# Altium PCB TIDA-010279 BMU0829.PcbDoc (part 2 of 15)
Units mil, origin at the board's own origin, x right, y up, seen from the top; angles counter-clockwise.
Board outline 11269.69 x 4438.98 mil, 4 copper layers (Top Layer, Signal Layer 1, Signal Layer 2, Bottom Layer), stack 61.6 mil thick; 1494 components, 725 nets, 3766 pads, 2728 vias.
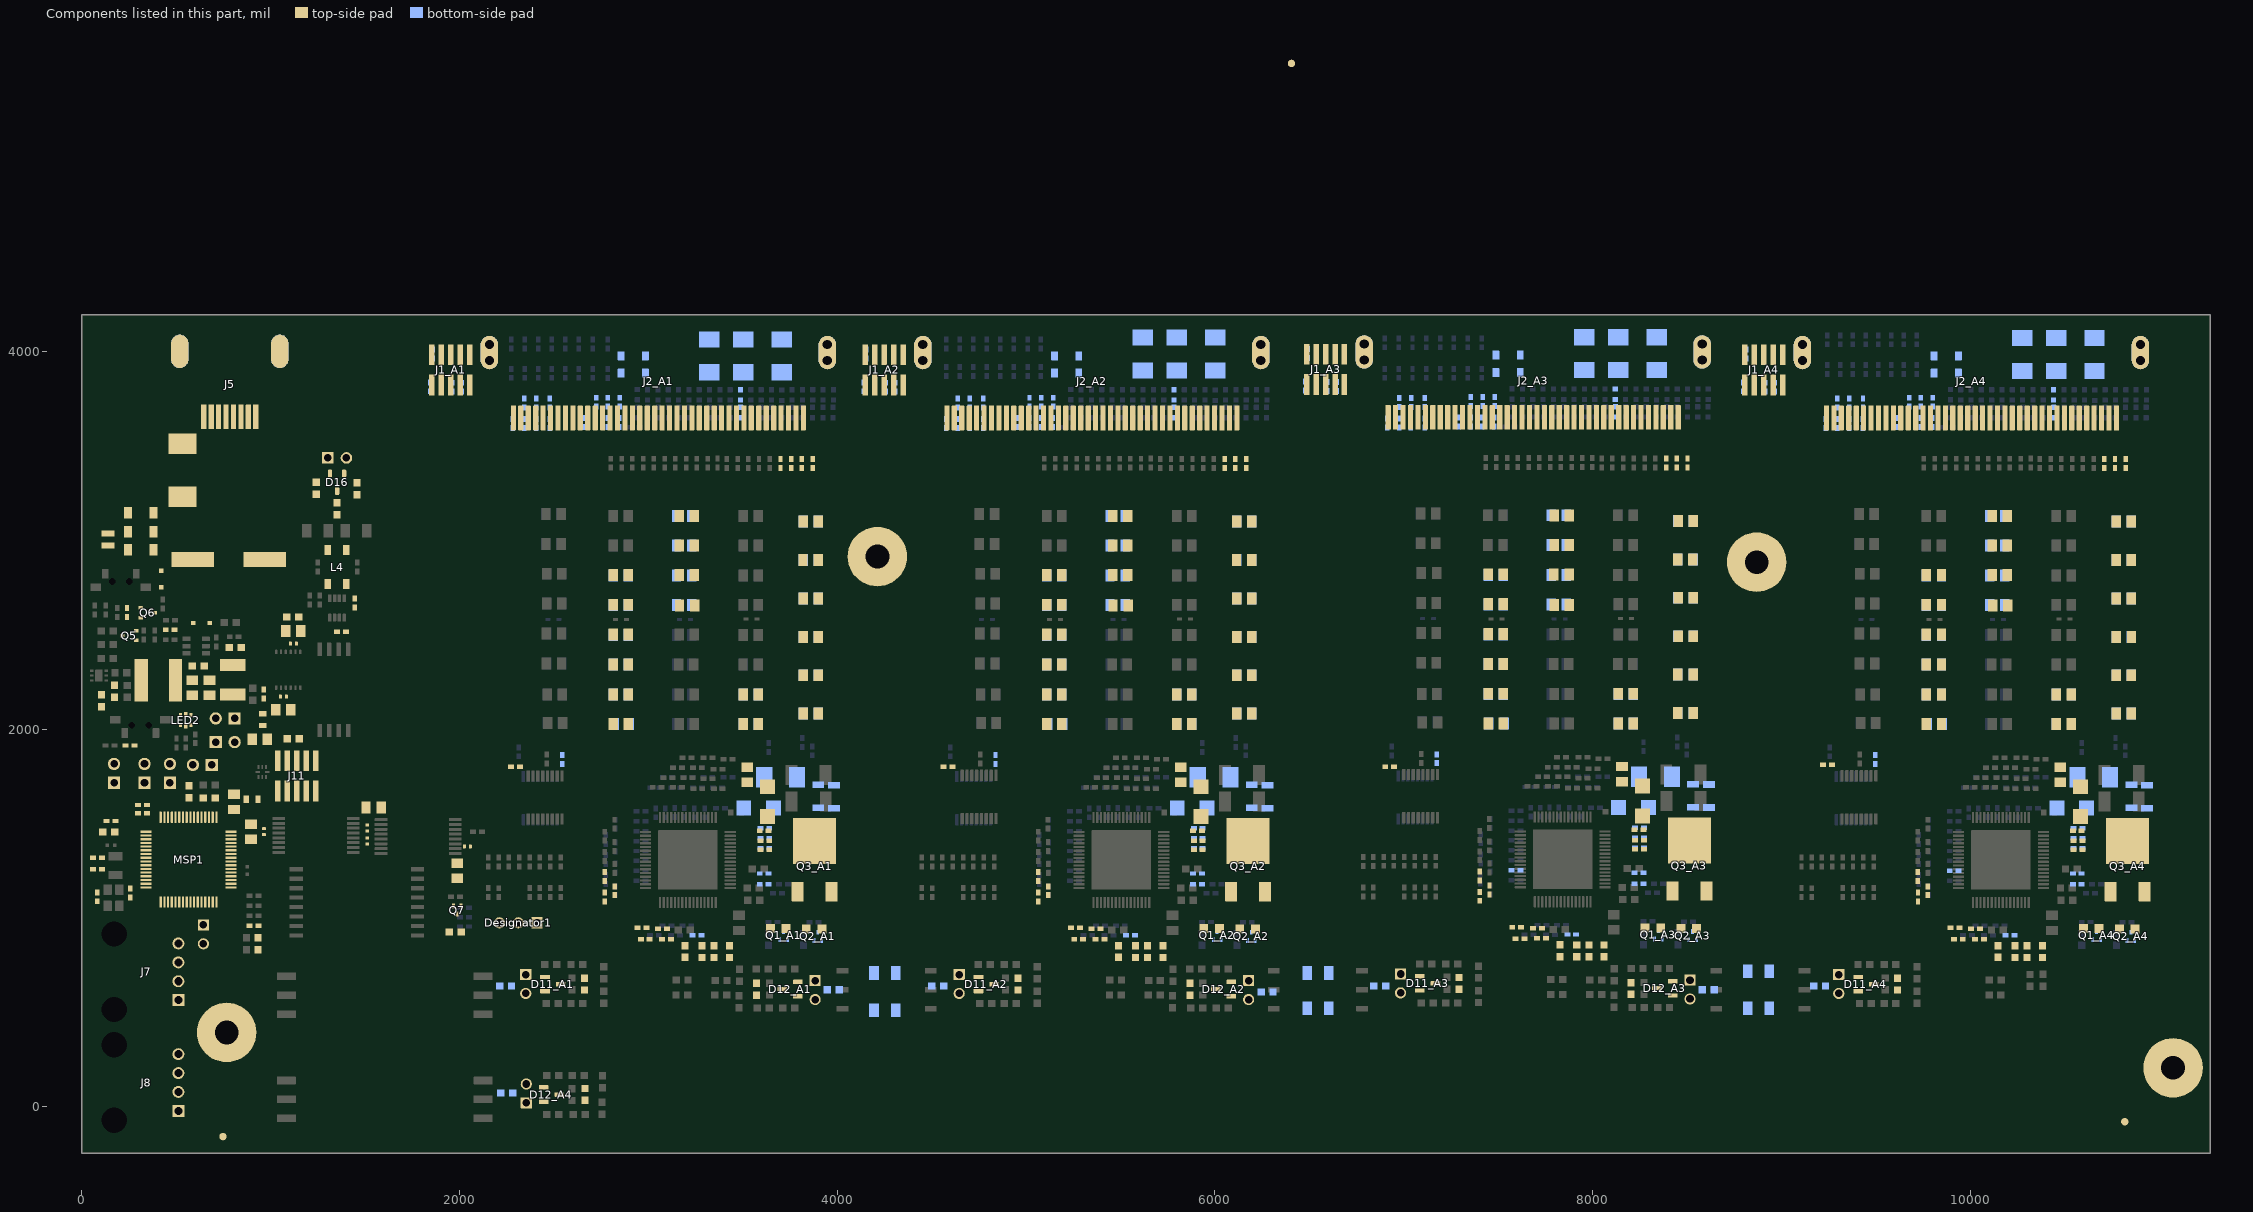
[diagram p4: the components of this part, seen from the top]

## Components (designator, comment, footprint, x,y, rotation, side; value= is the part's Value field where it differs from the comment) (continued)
C97_A3 "GCM155R71H104KE02D" 0402 7593.71,1252.59 r180 bottom value=0.1uF (schematic designator C97)
C97_A4 "GCM155R71H104KE02D" 0402 9913.94,1249.38 r180 bottom value=0.1uF (schematic designator C97)
C98_A1 "GCM155R71H472KA37D" 0402 2769.59,1219.43 r270 top value=4700pF (schematic designator C98)
C98_A2 "GCM155R71H472KA37D" 0402 5064.61,1219.43 r270 top value=4700pF (schematic designator C98)
C98_A3 "GCM155R71H472KA37D" 0402 7401.21,1222.64 r270 top value=4700pF (schematic designator C98)
C98_A4 "GCM155R71H472KA37D" 0402 9721.44,1219.43 r270 top value=4700pF (schematic designator C98)
C99_A1 "CGA3E2X7R2A223K080AA" FP-CGA3E2X7R2A223K080AA_0603-MFG 3488.75,3676.14 r90 bottom value=22nF (schematic designator C99)
C99_A2 "CGA3E2X7R2A223K080AA" FP-CGA3E2X7R2A223K080AA_0603-MFG 5783.76,3676.14 r90 bottom value=22nF (schematic designator C99)
C99_A3 "CGA3E2X7R2A223K080AA" FP-CGA3E2X7R2A223K080AA_0603-MFG 8120.36,3679.34 r90 bottom value=22nF (schematic designator C99)
C99_A4 "CGA3E2X7R2A223K080AA" FP-CGA3E2X7R2A223K080AA_0603-MFG 10440.59,3676.14 r90 bottom value=22nF (schematic designator C99)
C100_A1 "CGA3E2X7R2A223K080AA" FP-CGA3E2X7R2A223K080AA_0603-MFG 3488.04,3769.17 r90 bottom value=22nF (schematic designator C100)
C100_A2 "CGA3E2X7R2A223K080AA" FP-CGA3E2X7R2A223K080AA_0603-MFG 5783.06,3769.17 r90 bottom value=22nF (schematic designator C100)
C100_A3 "CGA3E2X7R2A223K080AA" FP-CGA3E2X7R2A223K080AA_0603-MFG 8119.66,3772.38 r90 bottom value=22nF (schematic designator C100)
C100_A4 "CGA3E2X7R2A223K080AA" FP-CGA3E2X7R2A223K080AA_0603-MFG 10439.89,3769.17 r90 bottom value=22nF (schematic designator C100)
C101_A1 "GCM155R71H472KA37D" 0402 2821.79,1144.09 r270 top value=4700pF (schematic designator C101)
C101_A2 "GCM155R71H472KA37D" 0402 5116.8,1144.09 r270 top value=4700pF (schematic designator C101)
C101_A3 "GCM155R71H472KA37D" 0402 7453.4,1147.3 r270 top value=4700pF (schematic designator C101)
C101_A4 "GCM155R71H472KA37D" 0402 9773.63,1144.09 r270 top value=4700pF (schematic designator C101)
C102_A1 "GCM155R71H472KA37D" 0402 2770.21,1111.63 r270 top value=4700pF (schematic designator C102)
C102_A2 "GCM155R71H472KA37D" 0402 5065.23,1111.63 r270 top value=4700pF (schematic designator C102)
C102_A3 "GCM155R71H472KA37D" 0402 7401.82,1114.83 r270 top value=4700pF (schematic designator C102)
C102_A4 "GCM155R71H472KA37D" 0402 9722.05,1111.63 r270 top value=4700pF (schematic designator C102)
C103_A1 "GCM155R71H104KE02D" 0402 3257.38,909.3 r0 bottom value=0.1uF (schematic designator C103)
C103_A2 "GCM155R71H104KE02D" 0402 5552.4,909.3 r0 bottom value=0.1uF (schematic designator C103)
C103_A3 "GCM155R71H104KE02D" 0402 7888.99,912.51 r0 bottom value=0.1uF (schematic designator C103)
C103_A4 "GCM155R71H104KE02D" 0402 10209.22,909.3 r0 bottom value=0.1uF (schematic designator C103)
C104_A1 "GCM155R71H472KA37D" 0402 2965.83,947.96 r0 top value=4700pF (schematic designator C104)
C104_A2 "GCM155R71H472KA37D" 0402 5260.84,947.96 r0 top value=4700pF (schematic designator C104)
C104_A3 "GCM155R71H472KA37D" 0402 7597.44,951.17 r0 top value=4700pF (schematic designator C104)
C104_A4 "GCM155R71H472KA37D" 0402 9917.67,947.96 r0 top value=4700pF (schematic designator C104)
C105_A1 "GCM155R71H472KA37D" 0402 2983.59,887.19 r0 top value=4700pF (schematic designator C105)
C105_A2 "GCM155R71H472KA37D" 0402 5278.61,887.19 r0 top value=4700pF (schematic designator C105)
C105_A3 "GCM155R71H472KA37D" 0402 7615.2,890.4 r0 top value=4700pF (schematic designator C105)
C105_A4 "GCM155R71H472KA37D" 0402 9935.43,887.19 r0 top value=4700pF (schematic designator C105)
C106_A1 "GCM155R71H472KA37D" 0402 3075.53,942.93 r0 top value=4700pF (schematic designator C106)
C106_A2 "GCM155R71H472KA37D" 0402 5370.55,942.93 r0 top value=4700pF (schematic designator C106)
C106_A3 "GCM155R71H472KA37D" 0402 7707.15,946.14 r0 top value=4700pF (schematic designator C106)
C106_A4 "GCM155R71H472KA37D" 0402 10027.38,942.93 r0 top value=4700pF (schematic designator C106)
C107_A1 "GCM155R71H472KA37D" 0402 3096.49,888.51 r0 top value=4700pF (schematic designator C107)
C107_A2 "GCM155R71H472KA37D" 0402 5391.5,888.51 r0 top value=4700pF (schematic designator C107)
C107_A3 "GCM155R71H472KA37D" 0402 7728.1,891.71 r0 top value=4700pF (schematic designator C107)
C107_A4 "GCM155R71H472KA37D" 0402 10048.33,888.51 r0 top value=4700pF (schematic designator C107)
C108_A1 "GCM155R71H104KE02D" 0402 2478.31,3617.56 r90 bottom value=0.1uF (schematic designator C108)
C108_A2 "GCM155R71H104KE02D" 0402 4773.32,3617.56 r90 bottom value=0.1uF (schematic designator C108)
C108_A3 "GCM155R71H104KE02D" 0402 7109.92,3620.76 r90 bottom value=0.1uF (schematic designator C108)
C108_A4 "GCM155R71H104KE02D" 0402 9430.15,3617.56 r90 bottom value=0.1uF (schematic designator C108)
C109_A1 "GCM155R71H104KE02D" 0402 2846.81,3622.34 r90 bottom value=0.1uF (schematic designator C109)
C109_A2 "GCM155R71H104KE02D" 0402 5141.83,3622.34 r90 bottom value=0.1uF (schematic designator C109)
C109_A3 "GCM155R71H104KE02D" 0402 7478.42,3625.55 r90 bottom value=0.1uF (schematic designator C109)
C109_A4 "GCM155R71H104KE02D" 0402 9798.65,3622.34 r90 bottom value=0.1uF (schematic designator C109)
C110_A1 "GCM155R71H104KE02D" 0402 3613.46,1178.02 r0 bottom value=0.1uF (schematic designator C110)
C110_A2 "GCM155R71H104KE02D" 0402 5908.48,1178.02 r0 bottom value=0.1uF (schematic designator C110)
C110_A3 "GCM155R71H104KE02D" 0402 8245.08,1181.23 r0 bottom value=0.1uF (schematic designator C110)
C110_A4 "GCM155R71H104KE02D" 0402 10565.31,1178.02 r0 bottom value=0.1uF (schematic designator C110)
C111_A1 "GCM155R71H104KE02D" 0402 2479.2,3725.82 r90 bottom value=0.1uF (schematic designator C111)
C111_A2 "GCM155R71H104KE02D" 0402 4774.22,3725.82 r90 bottom value=0.1uF (schematic designator C111)
C111_A3 "GCM155R71H104KE02D" 0402 7110.82,3729.03 r90 bottom value=0.1uF (schematic designator C111)
C111_A4 "GCM155R71H104KE02D" 0402 9431.05,3725.82 r90 bottom value=0.1uF (schematic designator C111)
C112_A1 "GCM155R71H104KE02D" 0402 2848.51,3730.61 r90 bottom value=0.1uF (schematic designator C112)
C112_A2 "GCM155R71H104KE02D" 0402 5143.53,3730.61 r90 bottom value=0.1uF (schematic designator C112)
C112_A3 "GCM155R71H104KE02D" 0402 7480.13,3733.82 r90 bottom value=0.1uF (schematic designator C112)
C112_A4 "GCM155R71H104KE02D" 0402 9800.36,3730.61 r90 bottom value=0.1uF (schematic designator C112)
C113_A1 "GCM155R71H104KE02D" 0402 1859.8,3985.59 r270 bottom value=0.1uF (schematic designator C113)
C113_A2 "GCM155R71H104KE02D" 0402 4154.81,3985.59 r270 bottom value=0.1uF (schematic designator C113)
C113_A3 "GCM155R71H104KE02D" 0402 6491.41,3988.8 r270 bottom value=0.1uF (schematic designator C113)
C113_A4 "GCM155R71H104KE02D" 0402 8811.64,3985.59 r270 bottom value=0.1uF (schematic designator C113)
C114_A1 "GCM155R71H104KE02D" 0402 3613.46,1235.37 r0 bottom value=0.1uF (schematic designator C114)
C114_A2 "GCM155R71H104KE02D" 0402 5908.48,1235.37 r0 bottom value=0.1uF (schematic designator C114)
C114_A3 "GCM155R71H104KE02D" 0402 8245.08,1238.57 r0 bottom value=0.1uF (schematic designator C114)
C114_A4 "GCM155R71H104KE02D" 0402 10565.31,1235.37 r0 bottom value=0.1uF (schematic designator C114)
C115_A1 "GCM155R71H104KE02D" 0402 3616.52,1409.33 r180 top value=0.1uF (schematic designator C115)
C115_A2 "GCM155R71H104KE02D" 0402 5911.54,1409.33 r180 top value=0.1uF (schematic designator C115)
C115_A3 "GCM155R71H104KE02D" 0402 8248.14,1412.54 r180 top value=0.1uF (schematic designator C115)
C115_A4 "GCM155R71H104KE02D" 0402 10568.37,1409.33 r180 top value=0.1uF (schematic designator C115)
C116_A1 "GCM155R71H104KE02D" 0402 2405.97,3617.56 r90 bottom value=0.1uF (schematic designator C116)
C116_A2 "GCM155R71H104KE02D" 0402 4700.98,3617.56 r90 bottom value=0.1uF (schematic designator C116)
C116_A3 "GCM155R71H104KE02D" 0402 7037.58,3620.76 r90 bottom value=0.1uF (schematic designator C116)
C116_A4 "GCM155R71H104KE02D" 0402 9357.81,3617.56 r90 bottom value=0.1uF (schematic designator C116)
C117_A1 "GCM155R71H104KE02D" 0402 2784.32,3622.34 r90 bottom value=0.1uF (schematic designator C117)
C117_A2 "GCM155R71H104KE02D" 0402 5079.33,3622.34 r90 bottom value=0.1uF (schematic designator C117)
C117_A3 "GCM155R71H104KE02D" 0402 7415.93,3625.55 r90 bottom value=0.1uF (schematic designator C117)
C117_A4 "GCM155R71H104KE02D" 0402 9736.16,3622.34 r90 bottom value=0.1uF (schematic designator C117)
C118_A1 "GCM155R71H104KE02D" 0402 1845.97,3812.37 r90 bottom value=0.1uF (schematic designator C118)
C118_A2 "GCM155R71H104KE02D" 0402 4140.99,3812.37 r90 bottom value=0.1uF (schematic designator C118)
C118_A3 "GCM155R71H104KE02D" 0402 6477.58,3815.58 r90 bottom value=0.1uF (schematic designator C118)
C118_A4 "GCM155R71H104KE02D" 0402 8797.81,3812.37 r90 bottom value=0.1uF (schematic designator C118)
C119_A1 "GCM155R71H104KE02D" 0402 3616.52,1474.8 r0 bottom value=0.1uF (schematic designator C119)
C119_A2 "GCM155R71H104KE02D" 0402 5911.54,1474.8 r0 bottom value=0.1uF (schematic designator C119)
C119_A3 "GCM155R71H104KE02D" 0402 8248.14,1478.01 r0 bottom value=0.1uF (schematic designator C119)
C119_A4 "GCM155R71H104KE02D" 0402 10568.37,1474.8 r0 bottom value=0.1uF (schematic designator C119)
C120_A1 "GCM155R71H104KE02D" 0402 2297.24,1801.18 r180 top value=0.1uF (schematic designator C120)
C120_A2 "GCM155R71H104KE02D" 0402 4586.61,1801.18 r180 top value=0.1uF (schematic designator C120)
C120_A3 "GCM155R71H104KE02D" 0402 6925.2,1801.18 r180 top value=0.1uF (schematic designator C120)
C120_A4 "GCM155R71H104KE02D" 0402 9242.13,1811.02 r180 top value=0.1uF (schematic designator C120)
C121_A1 "GCM155R71H104KE02D" 0402 2406.66,3725.82 r90 bottom value=0.1uF (schematic designator C121)
C121_A2 "GCM155R71H104KE02D" 0402 4701.68,3725.82 r90 bottom value=0.1uF (schematic designator C121)
C121_A3 "GCM155R71H104KE02D" 0402 7038.28,3729.03 r90 bottom value=0.1uF (schematic designator C121)
C121_A4 "GCM155R71H104KE02D" 0402 9358.51,3725.82 r90 bottom value=0.1uF (schematic designator C121)
C122_A1 "GCM155R71H104KE02D" 0402 2785.82,3730.61 r90 bottom value=0.1uF (schematic designator C122)
C122_A2 "GCM155R71H104KE02D" 0402 5080.83,3730.61 r90 bottom value=0.1uF (schematic designator C122)
C122_A3 "GCM155R71H104KE02D" 0402 7417.43,3733.82 r90 bottom value=0.1uF (schematic designator C122)
C122_A4 "GCM155R71H104KE02D" 0402 9737.66,3730.61 r90 bottom value=0.1uF (schematic designator C122)
C123_A1 "GCM155R71H104KE02D" 0402 2005.4,3982.92 r270 bottom value=0.1uF (schematic designator C123)
C123_A2 "GCM155R71H104KE02D" 0402 4300.42,3982.92 r270 bottom value=0.1uF (schematic designator C123)
C123_A3 "GCM155R71H104KE02D" 0402 6637.01,3986.12 r270 bottom value=0.1uF (schematic designator C123)
C123_A4 "GCM155R71H104KE02D" 0402 8957.24,3982.92 r270 bottom value=0.1uF (schematic designator C123)
C124_A1 "GCM155R71H104KE02D" 0402 3616.52,1422.9 r0 bottom value=0.1uF (schematic designator C124)
C124_A2 "GCM155R71H104KE02D" 0402 5911.54,1422.9 r0 bottom value=0.1uF (schematic designator C124)
C124_A3 "GCM155R71H104KE02D" 0402 8248.14,1426.11 r0 bottom value=0.1uF (schematic designator C124)
C124_A4 "GCM155R71H104KE02D" 0402 10568.37,1422.9 r0 bottom value=0.1uF (schematic designator C124)
C125_A1 "885012208118" WCAP-CSGP_1206_L3.2W1.6H1.25 3899.74,1644.24 r270 bottom (schematic designator C125)
C125_A2 "885012208118" WCAP-CSGP_1206_L3.2W1.6H1.25 6194.75,1644.24 r270 bottom (schematic designator C125)
C125_A3 "885012208118" WCAP-CSGP_1206_L3.2W1.6H1.25 8531.35,1647.45 r270 bottom (schematic designator C125)
C125_A4 "885012208118" WCAP-CSGP_1206_L3.2W1.6H1.25 10851.58,1644.24 r270 bottom (schematic designator C125)
C126_A1 "GCM155R71H104KE02D" 0402 2343.47,3617.56 r90 bottom value=0.1uF (schematic designator C126)
C126_A2 "GCM155R71H104KE02D" 0402 4638.49,3617.56 r90 bottom value=0.1uF (schematic designator C126)
C126_A3 "GCM155R71H104KE02D" 0402 6975.09,3620.76 r90 bottom value=0.1uF (schematic designator C126)
C126_A4 "GCM155R71H104KE02D" 0402 9295.32,3617.56 r90 bottom value=0.1uF (schematic designator C126)
C127_A1 "GCM155R71H104KE02D" 0402 2721.82,3622.34 r90 bottom value=0.1uF (schematic designator C127)
C127_A2 "GCM155R71H104KE02D" 0402 5016.84,3622.34 r90 bottom value=0.1uF (schematic designator C127)
C127_A3 "GCM155R71H104KE02D" 0402 7353.43,3625.55 r90 bottom value=0.1uF (schematic designator C127)
C127_A4 "GCM155R71H104KE02D" 0402 9673.66,3622.34 r90 bottom value=0.1uF (schematic designator C127)
C128_A1 "GCM155R71H104KE02D" 0402 2011.97,3810.12 r90 bottom value=0.1uF (schematic designator C128)
C128_A2 "GCM155R71H104KE02D" 0402 4306.99,3810.12 r90 bottom value=0.1uF (schematic designator C128)
C128_A3 "GCM155R71H104KE02D" 0402 6643.58,3813.32 r90 bottom value=0.1uF (schematic designator C128)
C128_A4 "GCM155R71H104KE02D" 0402 8963.81,3810.12 r90 bottom value=0.1uF (schematic designator C128)
C129_A1 "GCM155R71H104KE02D" 0402 3616.52,1369.24 r0 bottom value=0.1uF (schematic designator C129)
C129_A2 "GCM155R71H104KE02D" 0402 5911.54,1369.24 r0 bottom value=0.1uF (schematic designator C129)
C129_A3 "GCM155R71H104KE02D" 0402 8248.14,1372.45 r0 bottom value=0.1uF (schematic designator C129)
C129_A4 "GCM155R71H104KE02D" 0402 10568.37,1369.24 r0 bottom value=0.1uF (schematic designator C129)
C130_A1 "GCM155R71H104KE02D" 0402 2343.97,3725.82 r90 bottom value=0.1uF (schematic designator C130)
C130_A2 "GCM155R71H104KE02D" 0402 4638.98,3725.82 r90 bottom value=0.1uF (schematic designator C130)
C130_A3 "GCM155R71H104KE02D" 0402 6975.58,3729.03 r90 bottom value=0.1uF (schematic designator C130)
C130_A4 "GCM155R71H104KE02D" 0402 9295.81,3725.82 r90 bottom value=0.1uF (schematic designator C130)
C131_A1 "GCM155R71H104KE02D" 0402 2723.12,3730.61 r90 bottom value=0.1uF (schematic designator C131)
C131_A2 "GCM155R71H104KE02D" 0402 5018.14,3730.61 r90 bottom value=0.1uF (schematic designator C131)
C131_A3 "GCM155R71H104KE02D" 0402 7354.73,3733.82 r90 bottom value=0.1uF (schematic designator C131)
C131_A4 "GCM155R71H104KE02D" 0402 9674.96,3730.61 r90 bottom value=0.1uF (schematic designator C131)
C132_A1 "GCM155R71H104KE02D" 0402 1961.97,3810.12 r90 bottom value=0.1uF (schematic designator C132)
C132_A2 "GCM155R71H104KE02D" 0402 4256.99,3810.12 r90 bottom value=0.1uF (schematic designator C132)
C132_A3 "GCM155R71H104KE02D" 0402 6593.58,3813.32 r90 bottom value=0.1uF (schematic designator C132)
C132_A4 "GCM155R71H104KE02D" 0402 8913.81,3810.12 r90 bottom value=0.1uF (schematic designator C132)
C133_A1 "GCM155R71H104KE02D" 0402 3613.46,1462.99 r0 top value=0.1uF (schematic designator C133)
C133_A2 "GCM155R71H104KE02D" 0402 5908.48,1462.99 r0 top value=0.1uF (schematic designator C133)
C133_A3 "GCM155R71H104KE02D" 0402 8245.08,1466.2 r0 top value=0.1uF (schematic designator C133)
C133_A4 "GCM155R71H104KE02D" 0402 10565.31,1462.99 r0 top value=0.1uF (schematic designator C133)
C135_A1 "GCM155R71H104KE02D" 0402 3616.52,1360.65 r180 top value=0.1uF (schematic designator C135)
C135_A2 "GCM155R71H104KE02D" 0402 5911.54,1360.65 r180 top value=0.1uF (schematic designator C135)
C135_A3 "GCM155R71H104KE02D" 0402 8248.14,1363.85 r180 top value=0.1uF (schematic designator C135)
C135_A4 "GCM155R71H104KE02D" 0402 10568.37,1360.65 r180 top value=0.1uF (schematic designator C135)
C136_A1 "GCM155R71H104KE02D" 0402 2280.98,3617.56 r90 bottom value=0.1uF (schematic designator C136)
C136_A2 "GCM155R71H104KE02D" 0402 4575.99,3617.56 r90 bottom value=0.1uF (schematic designator C136)
C136_A3 "GCM155R71H104KE02D" 0402 6912.59,3620.76 r90 bottom value=0.1uF (schematic designator C136)
C136_A4 "GCM155R71H104KE02D" 0402 9232.82,3617.56 r90 bottom value=0.1uF (schematic designator C136)
C137_A1 "GCM155R71H104KE02D" 0402 2659.32,3622.34 r90 bottom value=0.1uF (schematic designator C137)
C137_A2 "GCM155R71H104KE02D" 0402 4954.34,3622.34 r90 bottom value=0.1uF (schematic designator C137)
C137_A3 "GCM155R71H104KE02D" 0402 7290.94,3625.55 r90 bottom value=0.1uF (schematic designator C137)
C137_A4 "GCM155R71H104KE02D" 0402 9611.17,3622.34 r90 bottom value=0.1uF (schematic designator C137)
C138_A1 "GCM155R71H104KE02D" 0402 1904.13,3812.1 r90 bottom value=0.1uF (schematic designator C138)
C138_A2 "GCM155R71H104KE02D" 0402 4199.15,3812.1 r90 bottom value=0.1uF (schematic designator C138)
C138_A3 "GCM155R71H104KE02D" 0402 6535.75,3815.31 r90 bottom value=0.1uF (schematic designator C138)
C138_A4 "GCM155R71H104KE02D" 0402 8855.98,3812.1 r90 bottom value=0.1uF (schematic designator C138)
C140_A1 "GCM155R71H104KE02D" 0402 2543.08,1839.7 r90 bottom value=0.1uF (schematic designator C140)
C140_A2 "GCM155R71H104KE02D" 0402 4838.1,1839.7 r90 bottom value=0.1uF (schematic designator C140)
C140_A3 "GCM155R71H104KE02D" 0402 7174.69,1842.91 r90 bottom value=0.1uF (schematic designator C140)
C140_A4 "GCM155R71H104KE02D" 0402 9494.92,1839.7 r90 bottom value=0.1uF (schematic designator C140)
C147_A1 "GCM188R71H103KA37D" 0603 2661.35,650.13 r90 top value=0.01uF (schematic designator C147)
C147_A2 "GCM188R71H103KA37D" 0603 4956.37,650.13 r90 top value=0.01uF (schematic designator C147)
C147_A3 "GCM188R71H103KA37D" 0603 7292.96,653.33 r90 top value=0.01uF (schematic designator C147)
C147_A4 "GCM188R71H103KA37D" 0603 9613.19,650.13 r90 top value=0.01uF (schematic designator C147)
C148_A1 "GCM188R71H103KA37D" 0603 3571.8,623.34 r270 top value=0.01uF (schematic designator C148)
C148_A2 "GCM188R71H103KA37D" 0603 5866.81,623.34 r270 top value=0.01uF (schematic designator C148)
C148_A3 "GCM188R71H103KA37D" 0603 8203.41,626.54 r270 top value=0.01uF (schematic designator C148)
C148_A4 "GCM188R71H103KA37D" 0603 2665.33,65.64 r90 top value=0.01uF (schematic designator C148)
C149_A1 "CL10B221JB8NNNC" 0603 3283.85,822.24 r270 top value=220pF (schematic designator C149)
C149_A2 "CL10B221JB8NNNC" 0603 5578.86,822.24 r270 top value=220pF (schematic designator C149)
C149_A3 "CL10B221JB8NNNC" 0603 7915.46,825.45 r270 top value=220pF (schematic designator C149)
C149_A4 "CL10B221JB8NNNC" 0603 10235.69,822.24 r270 top value=220pF (schematic designator C149)
C150_A1 "CL10B221JB8NNNC" 0603 3347.63,822.3 r270 top value=220pF (schematic designator C150)
C150_A2 "CL10B221JB8NNNC" 0603 5642.65,822.3 r270 top value=220pF (schematic designator C150)
C150_A3 "CL10B221JB8NNNC" 0603 7979.24,825.51 r270 top value=220pF (schematic designator C150)
C150_A4 "CL10B221JB8NNNC" 0603 10299.47,822.3 r270 top value=220pF (schematic designator C150)
C151_A1 "CL10B221JB8NNNC" 0603 3429.04,822.3 r270 top value=220pF (schematic designator C151)
C151_A2 "CL10B221JB8NNNC" 0603 5724.05,822.3 r270 top value=220pF (schematic designator C151)
C151_A3 "CL10B221JB8NNNC" 0603 8060.65,825.51 r270 top value=220pF (schematic designator C151)
C151_A4 "CL10B221JB8NNNC" 0603 10380.88,822.3 r270 top value=220pF (schematic designator C151)
C152_A1 "CL10B221JB8NNNC" 0603 3194.84,822.43 r270 top value=220pF (schematic designator C152)
C152_A2 "CL10B221JB8NNNC" 0603 5489.86,822.43 r270 top value=220pF (schematic designator C152)
C152_A3 "CL10B221JB8NNNC" 0603 7826.46,825.64 r270 top value=220pF (schematic designator C152)
C152_A4 "CL10B221JB8NNNC" 0603 10146.69,822.43 r270 top value=220pF (schematic designator C152)
C153 "12061A222JAT2A" 1206 4251.97,708.66 r180 bottom value=2200pF
C154 "12061A222JAT2A" 1206 6545.28,708.66 r180 bottom value=2200pF
C155 "12061A222JAT2A" 1206 8877.95,718.5 r180 bottom value=2200pF
C156 "GCM1885C1H101JA16J" 0603 2244.09,639.76 r180 bottom value=100pF
C157 "GCM1885C1H101JA16J" 0603 3979.86,620.08 r0 bottom value=100pF
C158 "GCM1885C1H101JA16J" 0603 4532.72,640.91 r180 bottom value=100pF
C159 "GCM1885C1H101JA16J" 0603 6275.62,608.32 r0 bottom value=100pF
C160 "GCM1885C1H101JA16J" 0603 6872.05,639.76 r180 bottom value=100pF
C161 "GCM1885C1H101JA16J" 0603 8612.2,620.08 r0 bottom value=100pF
C162 "GCM1885C1H101JA16J" 0603 9200.79,639.76 r180 bottom value=100pF
C163 "12061A222JAT2A" 1206 4251.97,511.81 r0 bottom value=2200pF
C164 "12061A222JAT2A" 1206 6545.28,521.65 r0 bottom value=2200pF
C165 "12061A222JAT2A" 1206 8877.95,521.65 r0 bottom value=2200pF
C166 "GCM1885C1H101JA16J" 0603 2249.93,72.99 r180 bottom value=100pF
C167 "GRM188R60J106ME84" 0603 143.61,1454.71 r180 top value=10uF
C168 "GRM155R61H104ME14D" 0402 154.29,1513.33 r180 top value=0.1uF
C169 "GRM155R60J474KE19D" 0402 322.32,1598.07 r180 top value=0.47uF
C170 "GRM155R61H104ME14D" 0402 322.32,1555.39 r180 top value=0.1uF
C171 "GRM155R61C103KA01D" 0402 255.11,1913.14 r0 top value=0.01uF
C172 "C1608X5R1E105K080AC" 0603 674.85,1634.48 r0 top value=1uF
C173 "C1608X5R1E105K080AC" 0603 568.65,1667.95 r90 top value=1uF
C174 "GRM1555C1H220JA01D" 0402 83.14,1318.58 r0 top value=22pF
C175 "GRM1555C1H220JA01D" 0402 255.91,1131.89 r270 top value=22pF
C176 "GRM1555C1H220JA01D" 0402 82.99,1112.19 r90 top value=22pF
C177 "GRM1555C1H220JA01D" 0402 83.14,1258.51 r0 top value=22pF
C178 "EEV-TG2A470Q" Panasonic_H13 778.42,2897.5 r0 top value=47uF
C179 "C3216X7S2A225K160AB" 1206_180 312.36,3145.66 r0 top value=2.2uF
C180 "C3216X7S2A225K160AB" 1206_180 312.36,3044.8 r0 top value=2.2uF
C181 "C3216X7S2A225K160AB" 1206_180 312.36,2949.24 r0 top value=2.2uF
C182 "CGA3E2C0G1H220J080AA" 0603 812.25,2431.89 r180 top value=22pF
C183 "GRM21BZ71E106KE15L" 0805_HV 585.31,2219.73 r90 top value=10uF
C184 "CGA8P1X7R1E226M250KC" 1812_280 799.53,2261.54 r90 top value=22uF
C185 "GRM21BZ71A226ME15L" 0805_HV 942.76,1946.08 r0 top value=22uF
C186 "GRM21BZ71A226ME15L" 0805_HV 807.09,1614.17 r270 top value=22uF
C187 "GCM155R71H153KA55D" FP-GCM155R71H153KA55D_0402-MFG 1512.52,1475.78 r90 top value=15nF
C189 "GRM21BZ71A226ME15L" 0805_HV 1545.28,1584.65 r180 top value=22uF
C190 "GCM155R71H153KA55D" FP-GCM155R71H153KA55D_0402-MFG 1512.52,1406.88 r270 top value=15nF
C191_A1 "885012208118" WCAP-CSGP_1206_L3.2W1.6H1.25 3983.15,1642.23 r270 bottom (schematic designator C191)
C191_A2 "885012208118" WCAP-CSGP_1206_L3.2W1.6H1.25 6278.17,1642.23 r270 bottom (schematic designator C191)
C191_A3 "885012208118" WCAP-CSGP_1206_L3.2W1.6H1.25 8614.77,1645.44 r270 bottom (schematic designator C191)
C191_A4 "885012208118" WCAP-CSGP_1206_L3.2W1.6H1.25 10935,1642.23 r270 bottom (schematic designator C191)
C196 "GCM155R71H104KE02D" 0402 239.74,2618.05 r270 top value=0.1uF
C197 "GCM188R71C105KA64D" 0603 173.32,2200.57 r270 top value=1uF
C198 "GRT188R61C475KE13D" 0603 104.46,2149.67 r270 top value=4.7uF
C199 "GCM155R71H104KE02D" 0402 468.51,2527.01 r0 top value=0.1uF
C201 "06035C104KAT2A" 0603 1120.28,1948.73 r0 top value=0.1uF
C202 "06035C104KAT2A" 0603 1117.96,2593.41 r180 top value=0.1uF
C203 "GCM155R71H153KA55D" FP-GCM155R71H153KA55D_0402-MFG 1120.83,2452.76 r0 top value=15nF
C204 "GRM21BZ71A226ME15L" 0805_HV 1119.53,2518.39 r180 top value=22uF
C205 "GRM21BZ71A226ME15L" 0805_HV 1067.02,2102.33 r0 top value=22uF
C206 "GCM155R71H153KA55D" FP-GCM155R71H153KA55D_0402-MFG 1067.64,2172.12 r180 top value=15nF
C207 "GCM155R71H222KA37D" 0402 964.57,2185.04 r270 top value=2200pF
C211 "GCM155R71H153KA55D" FP-GCM155R71H153KA55D_0402-MFG 2041.56,1378.74 r180 top value=15nF
C212 "GRM21BZ71A226ME15L" 0805_HV 1988.19,1250.63 r270 top value=22uF
C213 "GRM21BZ71A226ME15L" 0805_HV 895.67,1456.69 r270 top value=22uF
C214 "GCM155R71H153KA55D" FP-GCM155R71H153KA55D_0402-MFG 964.57,1456.69 r90 top value=15nF
C215 "GCM155R71H222KA37D" 0402 911.42,958.55 r0 top value=2200pF
C216 "06035C104KAT2A" 0603 933.76,863.04 r90 top value=0.1uF
C217 "06035C104KAT2A" 0603 1978.35,925.2 r0 top value=0.1uF
C218 "GCM1885C1H680JA16D" 0603 1241.81,3274.57 r270 top value=68pF
C219 "GCM188R72A472KA37D" 0603 1351.97,3167.42 r90 top value=4700pF
C220 "GCM155R71A104KA55D" 0402 1375.07,2515.62 r0 top value=0.1uF
C221 "GCM1885C1H680JA16D" 0603 1457.91,3273.15 r90 top value=68pF
C222 "GCM155R71A104KA55D" 0402 1446.1,2667.99 r270 top value=0.1uF
CBoot1 "06035C104KAT2A" 0603 617.6,2334.37 r180 top value=0.1uF
CO1 "08055C104JAT2A" 0805_HV 676.04,2219.27 r90 top value=0.1uF
D1_A1 "ES1C-13-F" SMA 3584,1582.22 r0 bottom value=150V (schematic designator D1)
D1_A2 "ES1C-13-F" SMA 5879.02,1582.22 r0 bottom value=150V (schematic designator D1)
D1_A3 "ES1C-13-F" SMA 8215.62,1585.42 r0 bottom value=150V (schematic designator D1)
D1_A4 "ES1C-13-F" SMA 10535.85,1582.22 r0 bottom value=150V (schematic designator D1)
D2_A1 "LTST-C170KGKT" LTST-C170KGKT_Green 3687.03,943.19 r0 top value=Green (schematic designator D2)
D2_A2 "LTST-C170KGKT" LTST-C170KGKT_Green 5982.04,943.19 r0 top value=Green (schematic designator D2)
D2_A3 "LTST-C170KGKT" LTST-C170KGKT_Green 8318.64,946.39 r0 top value=Green (schematic designator D2)
D2_A4 "LTST-C170KGKT" LTST-C170KGKT_Green 10638.87,943.19 r0 top value=Green (schematic designator D2)
D3_A1 "LTST-C170KGKT" LTST-C170KGKT_Green 3877.43,941.68 r0 top value=Green (schematic designator D3)
D3_A2 "LTST-C170KGKT" LTST-C170KGKT_Green 6172.45,941.67 r0 top value=Green (schematic designator D3)
D3_A3 "LTST-C170KGKT" LTST-C170KGKT_Green 8509.04,944.88 r0 top value=Green (schematic designator D3)
D3_A4 "LTST-C170KGKT" LTST-C170KGKT_Green 10829.27,941.67 r0 top value=Green (schematic designator D3)
D4_A1 "SMD16PL-TP" FP-SMD16PL-TP_SOD123FL-MFG 2919.97,3976.38 r0 bottom (schematic designator D4)
D4_A2 "SMD16PL-TP" FP-SMD16PL-TP_SOD123FL-MFG 5214.99,3976.38 r0 bottom (schematic designator D4)
D4_A3 "SMD16PL-TP" FP-SMD16PL-TP_SOD123FL-MFG 7551.59,3979.59 r0 bottom (schematic designator D4)
D4_A4 "SMD16PL-TP" FP-SMD16PL-TP_SOD123FL-MFG 9871.82,3976.38 r0 bottom (schematic designator D4)
D5_A1 "SMD16PL-TP" FP-SMD16PL-TP_SOD123FL-MFG 2919.97,3884.6 r180 bottom (schematic designator D5)
D5_A2 "SMD16PL-TP" FP-SMD16PL-TP_SOD123FL-MFG 5214.99,3884.6 r180 bottom (schematic designator D5)
D5_A3 "SMD16PL-TP" FP-SMD16PL-TP_SOD123FL-MFG 7551.59,3887.81 r180 bottom (schematic designator D5)
D5_A4 "SMD16PL-TP" FP-SMD16PL-TP_SOD123FL-MFG 9871.82,3884.6 r180 bottom (schematic designator D5)
D6_A1 "SMBJ85A-13-F" SMB 3706.58,3976.38 r270 bottom value=85V (schematic designator D6)
D6_A2 "SMBJ85A-13-F" SMB 6001.28,3985.41 r270 bottom value=85V (schematic designator D6)
D6_A3 "SMBJ85A-13-F" SMB 8338.19,3987.59 r270 bottom value=85V (schematic designator D6)
D6_A4 "SMBJ85A-13-F" SMB 10656.64,3983.96 r270 bottom value=85V (schematic designator D6)
D7_A1 "SMBJ85A-13-F" SMB 3323.11,3976.38 r270 bottom value=85V (schematic designator D7)
D7_A2 "SMBJ85A-13-F" SMB 5617.8,3985.41 r270 bottom value=85V (schematic designator D7)
D7_A3 "SMBJ85A-13-F" SMB 7954.72,3987.59 r270 bottom value=85V (schematic designator D7)
D7_A4 "SMBJ85A-13-F" SMB 10273.17,3983.96 r270 bottom value=85V (schematic designator D7)
D8_A1 "SMBJ85A-13-F" SMB 3503.08,3976.38 r270 bottom value=85V (schematic designator D8)
D8_A2 "SMBJ85A-13-F" SMB 5797.78,3985.41 r270 bottom value=85V (schematic designator D8)
D8_A3 "SMBJ85A-13-F" SMB 8134.69,3987.59 r270 bottom value=85V (schematic designator D8)
D8_A4 "SMBJ85A-13-F" SMB 10453.14,3983.96 r270 bottom value=85V (schematic designator D8)
D9_A1 "SMAJ85A" SMA 3631.54,1616.25 r270 top value=85V (schematic designator D9)
D9_A2 "SMAJ85A" SMA 5926.55,1616.25 r270 top value=85V (schematic designator D9)
D9_A3 "SMAJ85A" SMA 8263.14,1619.46 r270 top value=85V (schematic designator D9)
D9_A4 "SMAJ85A" SMA 10583.37,1616.25 r270 top value=85V (schematic designator D9)
D10_A1 "SMBJ85A-13-F" SMB 3700.7,1744.01 r0 bottom value=85V (schematic designator D10)
D10_A2 "SMBJ85A-13-F" SMB 5995.71,1744.01 r0 bottom value=85V (schematic designator D10)
D10_A3 "SMBJ85A-13-F" SMB 8332.31,1747.22 r0 bottom value=85V (schematic designator D10)
D10_A4 "SMBJ85A-13-F" SMB 10652.54,1744.01 r0 bottom value=85V (schematic designator D10)
D11_A1 "ESD652DBZR" DBZ0003A-MFG 2494.5,650.13 r0 top (schematic designator D11)
D11_A2 "ESD652DBZR" DBZ0003A-MFG 4789.51,650.13 r0 top (schematic designator D11)
D11_A3 "ESD652DBZR" DBZ0003A-MFG 7126.11,653.33 r0 top (schematic designator D11)
D11_A4 "ESD652DBZR" DBZ0003A-MFG 9446.34,650.13 r0 top (schematic designator D11)
D12_A1 "ESD652DBZR" DBZ0003A-MFG 3750.16,623.73 r180 top (schematic designator D12)
D12_A2 "ESD652DBZR" DBZ0003A-MFG 6045.17,623.73 r180 top (schematic designator D12)
D12_A3 "ESD652DBZR" DBZ0003A-MFG 8381.77,626.94 r180 top (schematic designator D12)
D12_A4 "ESD652DBZR" DBZ0003A-MFG 2486.98,65.24 r0 top (schematic designator D12)
D13 "SMCJ33CA" SMC_Bi 533.47,3370.59 r90 top value=33V
D14 "1N4148WS-7-F" SOD-323 634.11,2561.74 r0 top value=75V
D15 "1N4148WS-7-F" SOD-323 421.01,2794.53 r90 top value=75V
D16 "NUP2105LT1G" SOT-23 1351.97,3306.61 r270 top value=24V
Designator1 "Comment" CONN_PEC03SAAN 2311.42,974.41 r180 top
FID1 "Fiducial" Fiducial10-20 6405.12,5524.33 r0 top
FID2 "Fiducial" Fiducial10-20 748.03,-157.48 r0 top
FID3 "Fiducial" Fiducial10-20 10816.93,-78.74 r0 top
H1 "NY PMS 440 0025 PH" "NY PMS 440 0025 PH" 4212.6,2913.39 r0 top locked
H2 "NY PMS 440 0025 PH" "NY PMS 440 0025 PH" 8868.11,2883.86 r0 top locked
H3 "NY PMS 440 0025 PH" "NY PMS 440 0025 PH" 767.72,393.7 r0 top locked
H4 "NY PMS 440 0025 PH" "NY PMS 440 0025 PH" 11072.83,206.69 r0 top locked
H5 "1902C" Keystone_1902C 4212.6,2913.39 r180 bottom locked
H6 "1902C" Keystone_1902C 8868.11,2883.86 r180 bottom locked
H7 "1902C" Keystone_1902C 767.72,393.7 r180 bottom locked
H8 "1902C" Keystone_1902C 11072.83,206.69 r180 bottom locked
H9 "SJ-5303 (CLEAR)" Bumpon_SJ5003Transparent 6555.12,5354.33 r180 bottom
H10 "SJ-5303 (CLEAR)" Bumpon_SJ5003Transparent 7696.85,5295.28 r180 bottom
H11 "SJ-5303 (CLEAR)" Bumpon_SJ5003Transparent 7148.27,5333.31 r180 bottom
H12 "SJ-5303 (CLEAR)" Bumpon_SJ5003Transparent 8208.66,5295.28 r180 bottom
J1_A1 "FTSH-105-01-L-DV-K" Samtec_FTSH-105-01-x-DV-K 1953.97,3901.37 r90 top (schematic designator J1)
J1_A2 "FTSH-105-01-L-DV-K" Samtec_FTSH-105-01-x-DV-K 4248.99,3901.37 r90 top (schematic designator J1)
J1_A3 "FTSH-105-01-L-DV-K" Samtec_FTSH-105-01-x-DV-K 6585.58,3904.57 r90 top (schematic designator J1)
J1_A4 "FTSH-105-01-L-DV-K" Samtec_FTSH-105-01-x-DV-K 8905.81,3901.37 r90 top (schematic designator J1)
J2_A1 "141114-214010" FP-141114-214010_HDR40-MFG 3053.26,3950.27 r180 top (schematic designator J2)
J2_A2 "141114-214010" FP-141114-214010_HDR40-MFG 5348.27,3950.27 r180 top (schematic designator J2)
J2_A3 "141114-214010" FP-141114-214010_HDR40-MFG 7684.87,3953.48 r180 top (schematic designator J2)
J2_A4 "141114-214010" FP-141114-214010_HDR40-MFG 10005.1,3950.27 r180 top (schematic designator J2)
J3_A1 "PEC02SAAN" CONN_PEC02SAAN 2350.88,650.27 r270 top (schematic designator J3)
J3_A2 "PEC02SAAN" CONN_PEC02SAAN 4645.87,650.27 r270 top (schematic designator J3)
J3_A3 "PEC02SAAN" CONN_PEC02SAAN 6982.47,653.48 r270 top (schematic designator J3)
J3_A4 "PEC02SAAN" CONN_PEC02SAAN 9302.7,650.27 r270 top (schematic designator J3)
J4_A1 "PEC02SAAN" CONN_PEC02SAAN 3883.27,618.03 r270 top (schematic designator J4)
J4_A2 "PEC02SAAN" CONN_PEC02SAAN 6178.29,618.03 r270 top (schematic designator J4)
J4_A3 "PEC02SAAN" CONN_PEC02SAAN 8514.89,621.24 r270 top (schematic designator J4)
J4_A4 "PEC02SAAN" CONN_PEC02SAAN 2353.86,70.95 r90 top (schematic designator J4)
J5 "141114-210810" FP-141114-210810_CONN_HDR16-MFG 783.84,3956.69 r180 top
J7 "70551-0038" Molex_70551-0038 511.81,714.92 r180 top
J8 "70551-0038" Molex_70551-0038 511.81,128.74 r180 top
J9 "90120-0122" CONN_90120-0122 171.17,1765.6 r90 top
J11 "FTSH-105-01-L-DV-K" Samtec_FTSH-105-01-x-DV-K 1138.86,1751.69 r270 top
J12 "90120-0122" CONN_90120-0122 759.8,1931.31 r0 top
J13 "90120-0122" CONN_90120-0122 759.36,2056.51 r180 top
J16 "PEC02SAAN" CONN_PEC02SAAN 644.34,913.32 r270 top
J17 "90120-0122" CONN_90120-0122 638.73,1810.3 r180 top
J18 "90120-0122" CONN_90120-0122 467.18,1765.6 r90 top
J20 "90120-0122" CONN_90120-0122 332.35,1765.6 r90 top
J21 "HTSW-102-09-G-S" Samtec_HTSW-102-09-x-S 1351.61,3435.53 r0 top
L2 "74479276210C" WE-PMCI_0806_L2W1.6H1 139,3003.31 r270 top
L3 "74404064330" WE-LQS_6045 406.31,2257.6 r180 top
L4 "ACT45B-510-2P-TL003" ACT45B_NoSilk 1351.96,2857.79 r90 top value=51uH
L5 "74479763222" WE-PMI_0603_L1.6W0.8H0.8 958.44,2050.07 r90 top
L6 "74479763222" WE-PMI_0603_L1.6W0.8H0.8 902.16,1629.66 r0 top
LBL1 "THT-14-423-10" Label_650x200 4891.73,39.37 r180 top
LED2 "19-337/R6GHBHC-A01/2T" 19-337_RGB 551.18,2047.24 r270 top value=RGB
Logo1 "Texas Instruments" TI_Stacked_Overlay_Small 6102.36,68.9 r0 top
Logo2 "CE Mark" CE_Mark_5mm 11463.49,523.08 r0 top
Logo3 "FCC disclaimer" FCC_disclaimer 1889.76,2312.99 r90 top
Logo4 "WEEE logo" WEEE_Minimum 7726.38,88.58 r0 top
MSP1 "MSPM0G3507SPM" PM0064A-MFG 565.6,1308.97 r180 top
Q1_A1 "RE1C002UNTCL" SC-89 3716.01,907.76 r90 bottom value=20V (schematic designator Q1)
Q1_A2 "RE1C002UNTCL" SC-89 6011.03,907.76 r90 bottom value=20V (schematic designator Q1)
Q1_A3 "RE1C002UNTCL" SC-89 8347.62,910.97 r90 bottom value=20V (schematic designator Q1)
Q1_A4 "RE1C002UNTCL" SC-89 10667.85,907.76 r90 bottom value=20V (schematic designator Q1)
Q2_A1 "RE1C002UNTCL" SC-89 3897.24,903.07 r90 bottom value=20V (schematic designator Q2)
Q2_A2 "RE1C002UNTCL" SC-89 6192.26,903.07 r90 bottom value=20V (schematic designator Q2)
Q2_A3 "RE1C002UNTCL" SC-89 8528.86,906.28 r90 bottom value=20V (schematic designator Q2)
Q2_A4 "RE1C002UNTCL" SC-89 10849.09,903.07 r90 bottom value=20V (schematic designator Q2)
Q3_A1 "CMP-0000504-4" DPAK 3880.05,1273.19 r90 top value="150 V" (schematic designator Q3)
Q3_A2 "CMP-0000504-4" DPAK 6175.07,1273.19 r90 top value="150 V" (schematic designator Q3)
Q3_A3 "CMP-0000504-4" DPAK 8511.66,1276.39 r90 top value="150 V" (schematic designator Q3)
Q3_A4 "CMP-0000504-4" DPAK 10831.89,1273.19 r90 top value="150 V" (schematic designator Q3)
Q5 "BSS84AKW,115" SOT-323 250.98,2495.33 r180 top value=-50V
Q6 "BC847BW,115" SOT-323 349.67,2615.55 r0 top value="45 V"
Q7 "RE1C002UNTCL" SC-89 1988.58,1041.54 r270 top value=20V
R1_A1 "HPCR0805J68R0KT" 0805_HV 2854.78,2816.48 r0 top value=68 (schematic designator R1)
R1_A2 "HPCR0805J68R0KT" 0805_HV 5149.8,2816.48 r0 top value=68 (schematic designator R1)
R1_A3 "HPCR0805J68R0KT" 0805_HV 7486.4,2819.69 r0 top value=68 (schematic designator R1)
R1_A4 "HPCR0805J68R0KT" 0805_HV 9806.63,2816.48 r0 top value=68 (schematic designator R1)
R2_A1 "HPCR0805J68R0KT" 0805_HV 3542.76,2184.04 r0 top value=68 (schematic designator R2)
R2_A2 "HPCR0805J68R0KT" 0805_HV 5837.78,2184.04 r0 top value=68 (schematic designator R2)
R2_A3 "HPCR0805J68R0KT" 0805_HV 8174.38,2187.25 r0 top value=68 (schematic designator R2)
R2_A4 "HPCR0805J68R0KT" 0805_HV 10494.6,2184.04 r0 top value=68 (schematic designator R2)
R3_A1 "HPCR0805J68R0KT" 0805_HV 3859.45,2895.38 r0 bottom value=68 (schematic designator R3)
R3_A2 "HPCR0805J68R0KT" 0805_HV 6154.47,2895.38 r0 bottom value=68 (schematic designator R3)
R3_A3 "HPCR0805J68R0KT" 0805_HV 8491.06,2898.58 r0 bottom value=68 (schematic designator R3)
R3_A4 "HPCR0805J68R0KT" 0805_HV 10811.29,2895.38 r0 bottom value=68 (schematic designator R3)
R4_A1 "HPCR0805J68R0KT" 0805_HV 2854.78,2658.37 r0 top value=68 (schematic designator R4)
R4_A2 "HPCR0805J68R0KT" 0805_HV 5149.8,2658.37 r0 top value=68 (schematic designator R4)
R4_A3 "HPCR0805J68R0KT" 0805_HV 7486.4,2661.58 r0 top value=68 (schematic designator R4)
R4_A4 "HPCR0805J68R0KT" 0805_HV 9806.63,2658.37 r0 top value=68 (schematic designator R4)
R5_A1 "HPCR0805J68R0KT" 0805_HV 3543.08,2025.93 r0 bottom value=68 (schematic designator R5)
R5_A2 "HPCR0805J68R0KT" 0805_HV 5838.1,2025.93 r0 bottom value=68 (schematic designator R5)
R5_A3 "HPCR0805J68R0KT" 0805_HV 8174.69,2029.14 r0 bottom value=68 (schematic designator R5)
R5_A4 "HPCR0805J68R0KT" 0805_HV 10494.92,2025.93 r0 bottom value=68 (schematic designator R5)
R6_A1 "HPCR0805J68R0KT" 0805_HV 3858.98,2895.5 r0 top value=68 (schematic designator R6)
R6_A2 "HPCR0805J68R0KT" 0805_HV 6154,2895.5 r0 top value=68 (schematic designator R6)
R6_A3 "HPCR0805J68R0KT" 0805_HV 8490.59,2898.71 r0 top value=68 (schematic designator R6)
R6_A4 "HPCR0805J68R0KT" 0805_HV 10810.82,2895.5 r0 top value=68 (schematic designator R6)
R7_A1 "HPCR0805J68R0KT" 0805_HV 2854.76,2656.12 r0 bottom value=68 (schematic designator R7)
R7_A2 "HPCR0805J68R0KT" 0805_HV 5149.78,2656.12 r0 bottom value=68 (schematic designator R7)
R7_A3 "HPCR0805J68R0KT" 0805_HV 7486.37,2659.32 r0 bottom value=68 (schematic designator R7)
R7_A4 "HPCR0805J68R0KT" 0805_HV 9806.6,2656.12 r0 bottom value=68 (schematic designator R7)
R8_A1 "HPCR0805J68R0KT" 0805_HV 3543.08,2183.48 r0 bottom value=68 (schematic designator R8)
R8_A2 "HPCR0805J68R0KT" 0805_HV 5838.1,2183.48 r0 bottom value=68 (schematic designator R8)
R8_A3 "HPCR0805J68R0KT" 0805_HV 8174.69,2186.69 r0 bottom value=68 (schematic designator R8)
R8_A4 "HPCR0805J68R0KT" 0805_HV 10494.92,2183.48 r0 bottom value=68 (schematic designator R8)
R9_A1 "HPCR0805J68R0KT" 0805_HV 3860.14,3098.81 r0 top value=68 (schematic designator R9)
R9_A2 "HPCR0805J68R0KT" 0805_HV 6155.16,3098.81 r0 top value=68 (schematic designator R9)
R9_A3 "HPCR0805J68R0KT" 0805_HV 8491.76,3102.01 r0 top value=68 (schematic designator R9)
R9_A4 "HPCR0805J68R0KT" 0805_HV 10811.99,3098.81 r0 top value=68 (schematic designator R9)
R10_A1 "HPCR0805J68R0KT" 0805_HV 2854.76,2813.66 r0 bottom value=68 (schematic designator R10)
R10_A2 "HPCR0805J68R0KT" 0805_HV 5149.78,2813.66 r0 bottom value=68 (schematic designator R10)
R10_A3 "HPCR0805J68R0KT" 0805_HV 7486.37,2816.87 r0 bottom value=68 (schematic designator R10)
R10_A4 "HPCR0805J68R0KT" 0805_HV 9806.6,2813.66 r0 bottom value=68 (schematic designator R10)
R11_A1 "HPCR0805J68R0KT" 0805_HV 3542.76,2025.93 r0 top value=68 (schematic designator R11)
R11_A2 "HPCR0805J68R0KT" 0805_HV 5837.78,2025.93 r0 top value=68 (schematic designator R11)
R11_A3 "HPCR0805J68R0KT" 0805_HV 8174.38,2029.14 r0 top value=68 (schematic designator R11)
R11_A4 "HPCR0805J68R0KT" 0805_HV 10494.6,2025.93 r0 top value=68 (schematic designator R11)
R12_A1 "HPCR0805J68R0KT" 0805_HV 3859.45,3098.81 r0 bottom value=68 (schematic designator R12)
R12_A2 "HPCR0805J68R0KT" 0805_HV 6154.47,3098.81 r0 bottom value=68 (schematic designator R12)
R12_A3 "HPCR0805J68R0KT" 0805_HV 8491.06,3102.01 r0 bottom value=68 (schematic designator R12)
R12_A4 "HPCR0805J68R0KT" 0805_HV 10811.29,3098.81 r0 bottom value=68 (schematic designator R12)
R13_A1 "HPCR0805J68R0KT" 0805_HV 2854.78,2342.15 r0 top value=68 (schematic designator R13)
R13_A2 "HPCR0805J68R0KT" 0805_HV 5149.8,2342.15 r0 top value=68 (schematic designator R13)
R13_A3 "HPCR0805J68R0KT" 0805_HV 7486.4,2345.36 r0 top value=68 (schematic designator R13)
R13_A4 "HPCR0805J68R0KT" 0805_HV 9806.63,2342.15 r0 top value=68 (schematic designator R13)
R14_A1 "HPCR0805J68R0KT" 0805_HV 3203.94,3128.18 r0 top value=68 (schematic designator R14)
R14_A2 "HPCR0805J68R0KT" 0805_HV 5498.96,3128.18 r0 top value=68 (schematic designator R14)
R14_A3 "HPCR0805J68R0KT" 0805_HV 7835.55,3131.39 r0 top value=68 (schematic designator R14)
R14_A4 "HPCR0805J68R0KT" 0805_HV 10155.78,3128.18 r0 top value=68 (schematic designator R14)
R15_A1 "HPCR0805J68R0KT" 0805_HV 3859.45,2691.94 r0 bottom value=68 (schematic designator R15)
R15_A2 "HPCR0805J68R0KT" 0805_HV 6154.47,2691.94 r0 bottom value=68 (schematic designator R15)
R15_A3 "HPCR0805J68R0KT" 0805_HV 8491.06,2695.15 r0 bottom value=68 (schematic designator R15)
R15_A4 "HPCR0805J68R0KT" 0805_HV 10811.29,2691.94 r0 bottom value=68 (schematic designator R15)
R16_A1 "HPCR0805J68R0KT" 0805_HV 2854.78,2500.26 r0 top value=68 (schematic designator R16)
R16_A2 "HPCR0805J68R0KT" 0805_HV 5149.8,2500.26 r0 top value=68 (schematic designator R16)
R16_A3 "HPCR0805J68R0KT" 0805_HV 7486.4,2503.47 r0 top value=68 (schematic designator R16)
R16_A4 "HPCR0805J68R0KT" 0805_HV 9806.63,2500.26 r0 top value=68 (schematic designator R16)
R17_A1 "HPCR0805J68R0KT" 0805_HV 3189.11,2971.21 r0 bottom value=68 (schematic designator R17)
R17_A2 "HPCR0805J68R0KT" 0805_HV 5484.12,2971.21 r0 bottom value=68 (schematic designator R17)
R17_A3 "HPCR0805J68R0KT" 0805_HV 7820.72,2974.42 r0 bottom value=68 (schematic designator R17)
R17_A4 "HPCR0805J68R0KT" 0805_HV 10140.95,2971.21 r0 bottom value=68 (schematic designator R17)
R18_A1 "HPCR0805J68R0KT" 0805_HV 3859.45,2488.51 r0 bottom value=68 (schematic designator R18)
R18_A2 "HPCR0805J68R0KT" 0805_HV 6154.47,2488.51 r0 bottom value=68 (schematic designator R18)
R18_A3 "HPCR0805J68R0KT" 0805_HV 8491.06,2491.72 r0 bottom value=68 (schematic designator R18)
R18_A4 "HPCR0805J68R0KT" 0805_HV 10811.29,2488.51 r0 bottom value=68 (schematic designator R18)
R19_A1 "CRCW04021K00FKED" 0402 3870.27,3405.51 r270 top value=1.00k (schematic designator R19)
R19_A2 "CRCW04021K00FKED" 0402 6165.29,3405.51 r270 top value=1.00k (schematic designator R19)
R19_A3 "CRCW04021K00FKED" 0402 8501.88,3408.72 r270 top value=1.00k (schematic designator R19)
R19_A4 "CRCW04021K00FKED" 0402 10822.11,3405.51 r270 top value=1.00k (schematic designator R19)
R20_A1 "HPCR0805J68R0KT" 0805_HV 2854.76,2341.02 r0 bottom value=68 (schematic designator R20)
R20_A2 "HPCR0805J68R0KT" 0805_HV 5149.78,2341.02 r0 bottom value=68 (schematic designator R20)
R20_A3 "HPCR0805J68R0KT" 0805_HV 7486.37,2344.23 r0 bottom value=68 (schematic designator R20)
R20_A4 "HPCR0805J68R0KT" 0805_HV 9806.6,2341.02 r0 bottom value=68 (schematic designator R20)
R21_A1 "HPCR0805J68R0KT" 0805_HV 3203.94,2971.21 r0 top value=68 (schematic designator R21)
R21_A2 "HPCR0805J68R0KT" 0805_HV 5498.96,2971.21 r0 top value=68 (schematic designator R21)
R21_A3 "HPCR0805J68R0KT" 0805_HV 7835.55,2974.42 r0 top value=68 (schematic designator R21)
R21_A4 "HPCR0805J68R0KT" 0805_HV 10155.78,2971.21 r0 top value=68 (schematic designator R21)
R22_A1 "HPCR0805J68R0KT" 0805_HV 3860.17,2691.94 r0 top value=68 (schematic designator R22)
R22_A2 "HPCR0805J68R0KT" 0805_HV 6155.19,2691.94 r0 top value=68 (schematic designator R22)
R22_A3 "HPCR0805J68R0KT" 0805_HV 8491.78,2695.15 r0 top value=68 (schematic designator R22)
R22_A4 "HPCR0805J68R0KT" 0805_HV 10812.01,2691.94 r0 top value=68 (schematic designator R22)
R23_A1 "HPCR0805J68R0KT" 0805_HV 2854.76,2498.57 r0 bottom value=68 (schematic designator R23)
R23_A2 "HPCR0805J68R0KT" 0805_HV 5149.78,2498.57 r0 bottom value=68 (schematic designator R23)
R23_A3 "HPCR0805J68R0KT" 0805_HV 7486.37,2501.78 r0 bottom value=68 (schematic designator R23)
R23_A4 "HPCR0805J68R0KT" 0805_HV 9806.6,2498.57 r0 bottom value=68 (schematic designator R23)
R24_A1 "HPCR0805J68R0KT" 0805_HV 3189.11,3128.75 r0 bottom value=68 (schematic designator R24)
R24_A2 "HPCR0805J68R0KT" 0805_HV 5484.12,3128.75 r0 bottom value=68 (schematic designator R24)
R24_A3 "HPCR0805J68R0KT" 0805_HV 7820.72,3131.96 r0 bottom value=68 (schematic designator R24)
R24_A4 "HPCR0805J68R0KT" 0805_HV 10140.95,3128.75 r0 bottom value=68 (schematic designator R24)
R25_A1 "HPCR0805J68R0KT" 0805_HV 3860.57,2488.51 r0 top value=68 (schematic designator R25)
R25_A2 "HPCR0805J68R0KT" 0805_HV 6155.59,2488.51 r0 top value=68 (schematic designator R25)
R25_A3 "HPCR0805J68R0KT" 0805_HV 8492.18,2491.72 r0 top value=68 (schematic designator R25)
R25_A4 "HPCR0805J68R0KT" 0805_HV 10812.41,2488.51 r0 top value=68 (schematic designator R25)
R26_A1 "CRCW04021K00FKED" 0402 3813.4,3405.51 r270 top value=1.00k (schematic designator R26)
R26_A2 "CRCW04021K00FKED" 0402 6108.42,3405.51 r270 top value=1.00k (schematic designator R26)
R26_A3 "CRCW04021K00FKED" 0402 8445.02,3408.72 r270 top value=1.00k (schematic designator R26)
R26_A4 "CRCW04021K00FKED" 0402 10765.25,3405.51 r270 top value=1.00k (schematic designator R26)
R27_A1 "HPCR0805J68R0KT" 0805_HV 2854.78,2025.93 r0 top value=68 (schematic designator R27)
R27_A2 "HPCR0805J68R0KT" 0805_HV 5149.8,2025.93 r0 top value=68 (schematic designator R27)
R27_A3 "HPCR0805J68R0KT" 0805_HV 7486.4,2029.14 r0 top value=68 (schematic designator R27)
R27_A4 "HPCR0805J68R0KT" 0805_HV 9806.63,2025.93 r0 top value=68 (schematic designator R27)
R28_A1 "HPCR0805J68R0KT" 0805_HV 3203.13,2815.51 r0 top value=68 (schematic designator R28)
R28_A2 "HPCR0805J68R0KT" 0805_HV 5498.15,2815.51 r0 top value=68 (schematic designator R28)
R28_A3 "HPCR0805J68R0KT" 0805_HV 7834.75,2818.72 r0 top value=68 (schematic designator R28)
R28_A4 "HPCR0805J68R0KT" 0805_HV 10154.98,2815.51 r0 top value=68 (schematic designator R28)
R29_A1 "HPCR0805J68R0KT" 0805_HV 3859.45,2285.08 r0 top value=68 (schematic designator R29)
R29_A2 "HPCR0805J68R0KT" 0805_HV 6154.47,2285.08 r0 top value=68 (schematic designator R29)
R29_A3 "HPCR0805J68R0KT" 0805_HV 8491.06,2288.29 r0 top value=68 (schematic designator R29)
R29_A4 "HPCR0805J68R0KT" 0805_HV 10811.29,2285.08 r0 top value=68 (schematic designator R29)
R30_A1 "HPCR0805J68R0KT" 0805_HV 2854.78,2184.04 r0 top value=68 (schematic designator R30)
R30_A2 "HPCR0805J68R0KT" 0805_HV 5149.8,2184.04 r0 top value=68 (schematic designator R30)
R30_A3 "HPCR0805J68R0KT" 0805_HV 7486.4,2187.25 r0 top value=68 (schematic designator R30)
R30_A4 "HPCR0805J68R0KT" 0805_HV 9806.63,2184.04 r0 top value=68 (schematic designator R30)
R31_A1 "HPCR0805J68R0KT" 0805_HV 3189.11,2813.66 r0 bottom value=68 (schematic designator R31)
R31_A2 "HPCR0805J68R0KT" 0805_HV 5484.12,2813.66 r0 bottom value=68 (schematic designator R31)
R31_A3 "HPCR0805J68R0KT" 0805_HV 7820.72,2816.87 r0 bottom value=68 (schematic designator R31)
R31_A4 "HPCR0805J68R0KT" 0805_HV 10140.95,2813.66 r0 bottom value=68 (schematic designator R31)
R32_A1 "HPCR0805J68R0KT" 0805_HV 3859.45,2285.08 r0 bottom value=68 (schematic designator R32)
R32_A2 "HPCR0805J68R0KT" 0805_HV 6154.47,2285.08 r0 bottom value=68 (schematic designator R32)
R32_A3 "HPCR0805J68R0KT" 0805_HV 8491.06,2288.29 r0 bottom value=68 (schematic designator R32)
R32_A4 "HPCR0805J68R0KT" 0805_HV 10811.29,2285.08 r0 bottom value=68 (schematic designator R32)
R33_A1 "HPCR0805J68R0KT" 0805_HV 2854.76,2183.48 r0 bottom value=68 (schematic designator R33)
R33_A2 "HPCR0805J68R0KT" 0805_HV 5149.78,2183.48 r0 bottom value=68 (schematic designator R33)
R33_A3 "HPCR0805J68R0KT" 0805_HV 7486.37,2186.69 r0 bottom value=68 (schematic designator R33)
R33_A4 "HPCR0805J68R0KT" 0805_HV 9806.6,2183.48 r0 bottom value=68 (schematic designator R33)
R34_A1 "HPCR0805J68R0KT" 0805_HV 3205.08,2653.85 r0 top value=68 (schematic designator R34)
R34_A2 "HPCR0805J68R0KT" 0805_HV 5500.09,2653.85 r0 top value=68 (schematic designator R34)
R34_A3 "HPCR0805J68R0KT" 0805_HV 7836.69,2657.06 r0 top value=68 (schematic designator R34)
R34_A4 "HPCR0805J68R0KT" 0805_HV 10156.92,2653.85 r0 top value=68 (schematic designator R34)
R35_A1 "HPCR0805J68R0KT" 0805_HV 3859.45,2081.65 r0 bottom value=68 (schematic designator R35)
R35_A2 "HPCR0805J68R0KT" 0805_HV 6154.47,2081.65 r0 bottom value=68 (schematic designator R35)
R35_A3 "HPCR0805J68R0KT" 0805_HV 8491.06,2084.86 r0 bottom value=68 (schematic designator R35)
R35_A4 "HPCR0805J68R0KT" 0805_HV 10811.29,2081.65 r0 bottom value=68 (schematic designator R35)
R36_A1 "CRCW080560R4FKEA" 0805_HV 3523.6,1758.86 r270 top value=60.4 (schematic designator R36)
R36_A2 "CRCW080560R4FKEA" 0805_HV 5818.62,1758.86 r270 top value=60.4 (schematic designator R36)
R36_A3 "CRCW080560R4FKEA" 0805_HV 8155.22,1762.07 r270 top value=60.4 (schematic designator R36)
R36_A4 "CRCW080560R4FKEA" 0805_HV 10475.45,1758.86 r270 top value=60.4 (schematic designator R36)
R37_A1 "CRCW04021K00FKED" 0402 3756.54,3405.51 r270 top value=1.00k (schematic designator R37)
R37_A2 "CRCW04021K00FKED" 0402 6051.55,3405.51 r270 top value=1.00k (schematic designator R37)
R37_A3 "CRCW04021K00FKED" 0402 8388.15,3408.72 r270 top value=1.00k (schematic designator R37)
R37_A4 "CRCW04021K00FKED" 0402 10708.38,3405.51 r270 top value=1.00k (schematic designator R37)
R38_A1 "HPCR0805J68R0KT" 0805_HV 2858.9,2025.93 r0 bottom value=68 (schematic designator R38)
R38_A2 "HPCR0805J68R0KT" 0805_HV 5153.92,2025.93 r0 bottom value=68 (schematic designator R38)
R38_A3 "HPCR0805J68R0KT" 0805_HV 7490.51,2029.14 r0 bottom value=68 (schematic designator R38)
R38_A4 "HPCR0805J68R0KT" 0805_HV 9810.74,2025.93 r0 bottom value=68 (schematic designator R38)
R39_A1 "HPCR0805J68R0KT" 0805_HV 3189.11,2656.12 r0 bottom value=68 (schematic designator R39)
R39_A2 "HPCR0805J68R0KT" 0805_HV 5484.12,2656.12 r0 bottom value=68 (schematic designator R39)
R39_A3 "HPCR0805J68R0KT" 0805_HV 7820.72,2659.32 r0 bottom value=68 (schematic designator R39)
R39_A4 "HPCR0805J68R0KT" 0805_HV 10140.95,2656.12 r0 bottom value=68 (schematic designator R39)
R40_A1 "HPCR0805J68R0KT" 0805_HV 3859.45,2081.65 r0 top value=68 (schematic designator R40)
R40_A2 "HPCR0805J68R0KT" 0805_HV 6154.47,2081.65 r0 top value=68 (schematic designator R40)
R40_A3 "HPCR0805J68R0KT" 0805_HV 8491.06,2084.86 r0 top value=68 (schematic designator R40)
R40_A4 "HPCR0805J68R0KT" 0805_HV 10811.29,2081.65 r0 top value=68 (schematic designator R40)
R41_A1 "CRCW04021K00FKED" 0402 3699.67,3405.51 r270 top value=1.00k (schematic designator R41)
